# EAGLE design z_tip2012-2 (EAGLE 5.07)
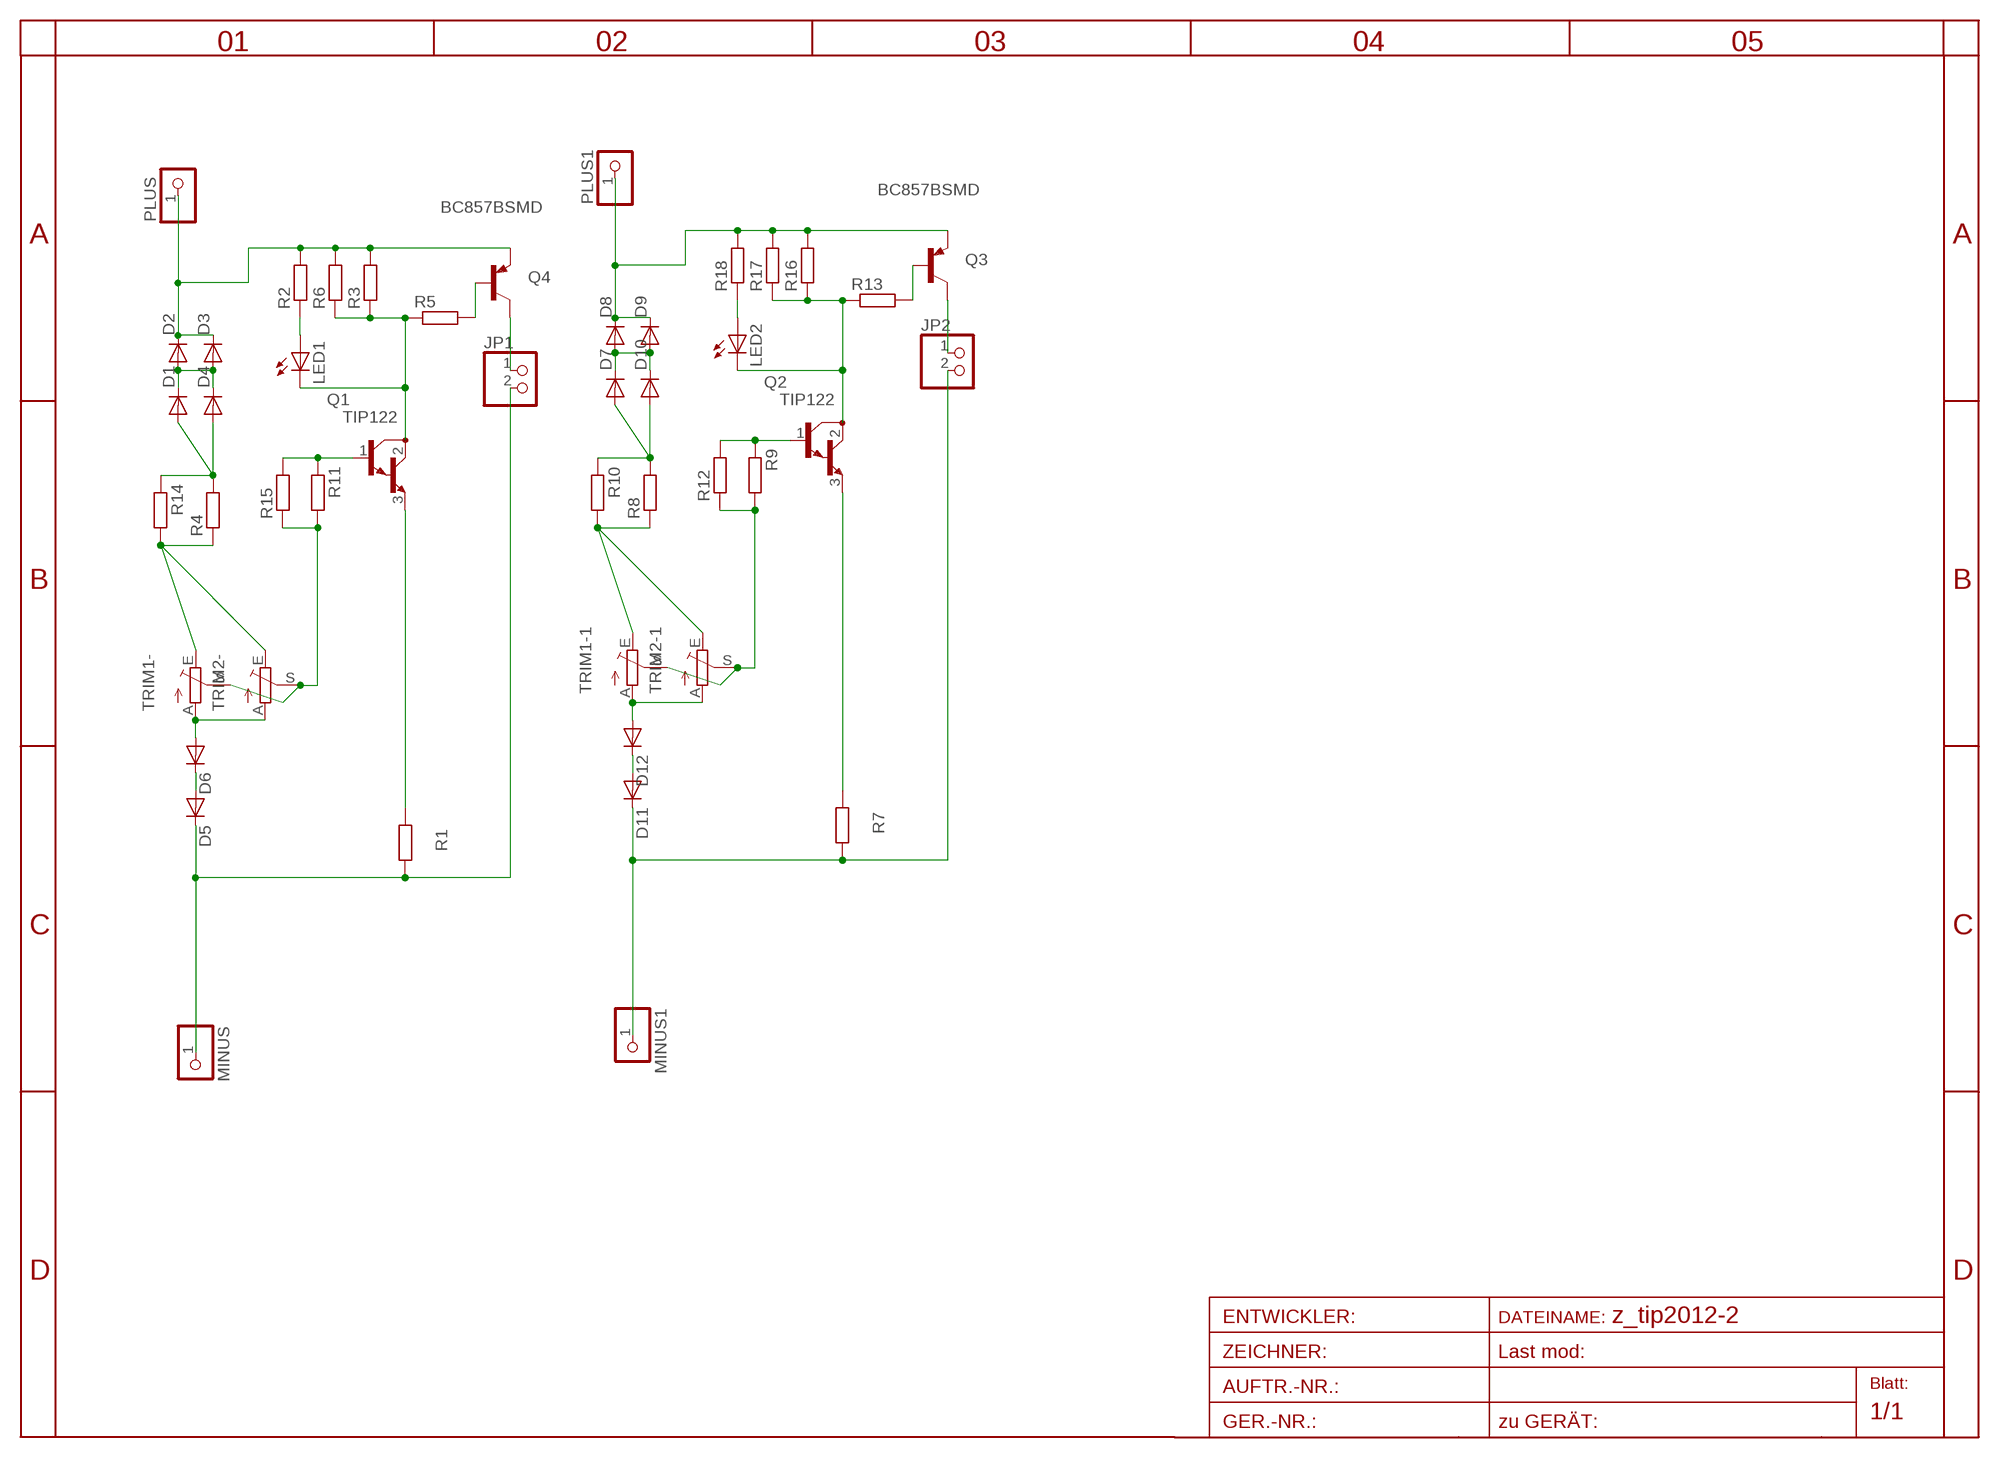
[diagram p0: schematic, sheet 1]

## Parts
D1  DIODE-MINIMELF  [MINIMELF]
D2  DIODE-MINIMELF  [MINIMELF]
D3  DIODE-D-2.5  [D-2.5]
D4  DIODE-D-2.5  [D-2.5]
D5  DIODE-MINIMELF  [MINIMELF]
D6  DIODE-MINIMELF  [MINIMELF]
D7  DIODE-MINIMELF  [MINIMELF]
D8  DIODE-MINIMELF  [MINIMELF]
D9  DIODE-D-2.5  [D-2.5]
D10  DIODE-D-2.5  [D-2.5]
D11  DIODE-MINIMELF  [MINIMELF]
D12  DIODE-MINIMELF  [MINIMELF]
JP1  PINHD-1X2  [1X02]
JP2  PINHD-1X2  [1X02]
LED1  LED3MM  [LED3MM]
LED2  LED3MM  [LED3MM]
MINUS  PINHD-1X10MM8  [1X01]
MINUS1  PINHD-1X10MM8  [1X01]
PLUS  PINHD-1X10MM8  [1X01]
PLUS1  PINHD-1X10MM8  [1X01]
Q1  TIP122  [TO220]
Q2  TIP122  [TO220]
Q3  BC857BSMD  [SOT23-BEC]
Q4  BC857BSMD  [SOT23-BEC]
R1  R-EU_0411/12  [0411/12]
R2  R-EU_R1206  [R1206]
R3  R-EU_CERAM55  [CERAM55]
R4  R-EU_R1206  [R1206]
R5  R-EU_R1206  [R1206]
R6  R-EU_CERAM55  [CERAM55]
R7  R-EU_0411/12  [0411/12]
R8  R-EU_R1206  [R1206]
R9  R-EU_0204/7  [0204/7]
R10  R-EU_0204/5  [0204/5]
R11  R-EU_0204/7  [0204/7]
R12  R-EU_R1206  [R1206]
R13  R-EU_R1206  [R1206]
R14  R-EU_0204/5  [0204/5]
R15  R-EU_R1206  [R1206]
R16  R-EU_CERAM55  [CERAM55]
R17  R-EU_CERAM55  [CERAM55]
R18  R-EU_R1206  [R1206]
TRIM1-  TRIM_EU-EVND_H  [EVND8AA]
TRIM1-1  TRIM_EU-CA6V  [CA6V]
TRIM2-  TRIM_EU-S64W  [S64W]
TRIM2-1  TRIM_EU-S64W  [S64W]

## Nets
B: R11.2 R15.1 TRIM1-.S TRIM2-.S
B1: R9.2 R12.1 TRIM1-1.S TRIM2-1.S
C: LED1.K(C) Q1.2(C) R3.1 R5.1 R6.1
C1: LED2.K(C) Q2.2(C) R13.1 R16.1 R17.1
E: Q1.3(E) R1.2
E1: Q2.3(E) R7.2
G: Q1.1(B) R11.1 R15.2
MINUS: D5.C JP1.2 MINUS.1 R1.1
MINUS1: D11.C JP2.2 MINUS1.1 R7.1
N$1: D1.A D4.A R4.2 R14.1
N$2: D1.C D2.A D3.A D4.C
N$3: R4.1 R14.2 TRIM1-.E TRIM2-.E
N$4: D5.A D6.C
N$6: LED1.A R2.1
N$7: D6.A TRIM1-.A TRIM2-.A
N$8: D7.C D8.A D9.A D10.C
N$9: Q4.B R5.2
N$11: R8.1 R10.2 TRIM1-1.E TRIM2-1.E
N$12: JP1.1 Q4.C
N$13: Q3.B R13.2
N$14: Q2.1(B) R9.1 R12.2
N$15: JP2.1 Q3.C
N$16: D7.A D10.A R8.2 R10.1
N$17: D11.A D12.C
N$18: LED2.A R18.1
N$19: D12.A TRIM1-1.A TRIM2-1.A
PLUS: D2.C D3.C PLUS.1 Q4.E R2.2 R3.2 R6.2
PLUS1: D8.C D9.C PLUS1.1 Q3.E R16.2 R17.2 R18.2

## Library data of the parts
D1-D12 = diode-1:DIODE-: DIODE
JP1 JP2 = pinhead:PINHD-1X2: PIN HEADER
LED1 LED2 = led:LED: LED
MINUS MINUS1 PLUS PLUS1 = pinhead:PINHD-1X1: PIN HEADER
Q1 Q2 = transistor-npn:TIP122*: NPN Darlington Transistor
Q3 Q4 = transistor-pnp:BC857*: PNP Transistror
R1-R18 = rcl:R-EU_: RESISTOR, European symbol
TRIM1- TRIM1-1 TRIM2- TRIM2-1 = pot:TRIM_EU-: POTENTIOMETER

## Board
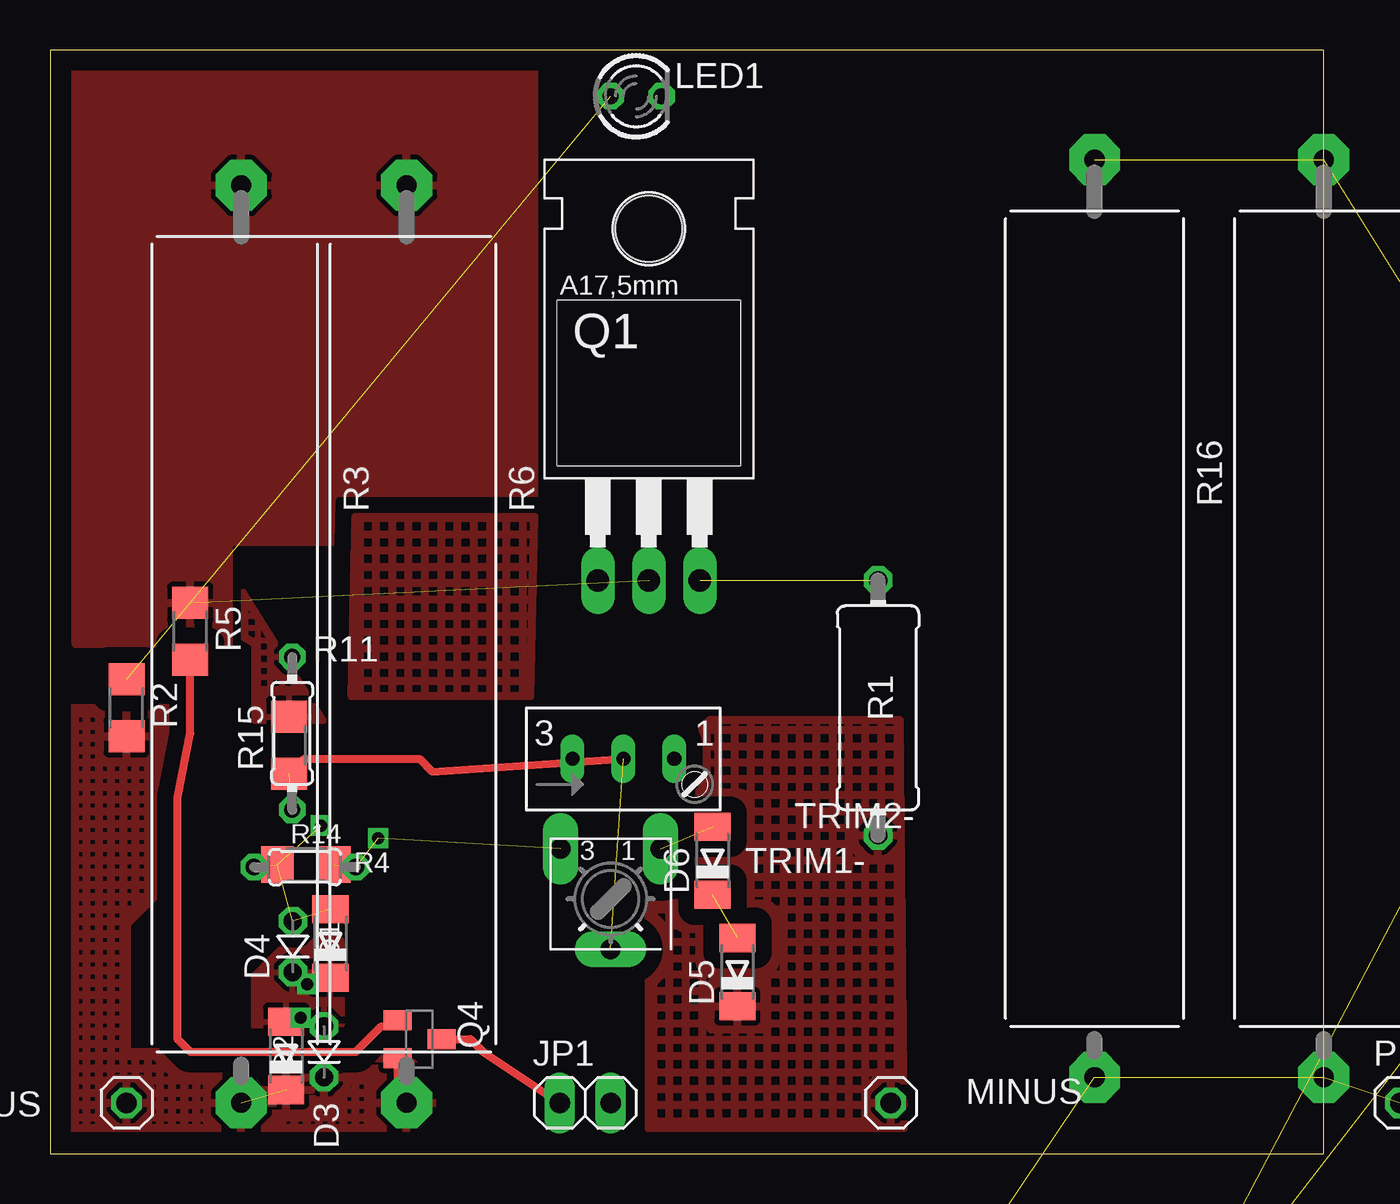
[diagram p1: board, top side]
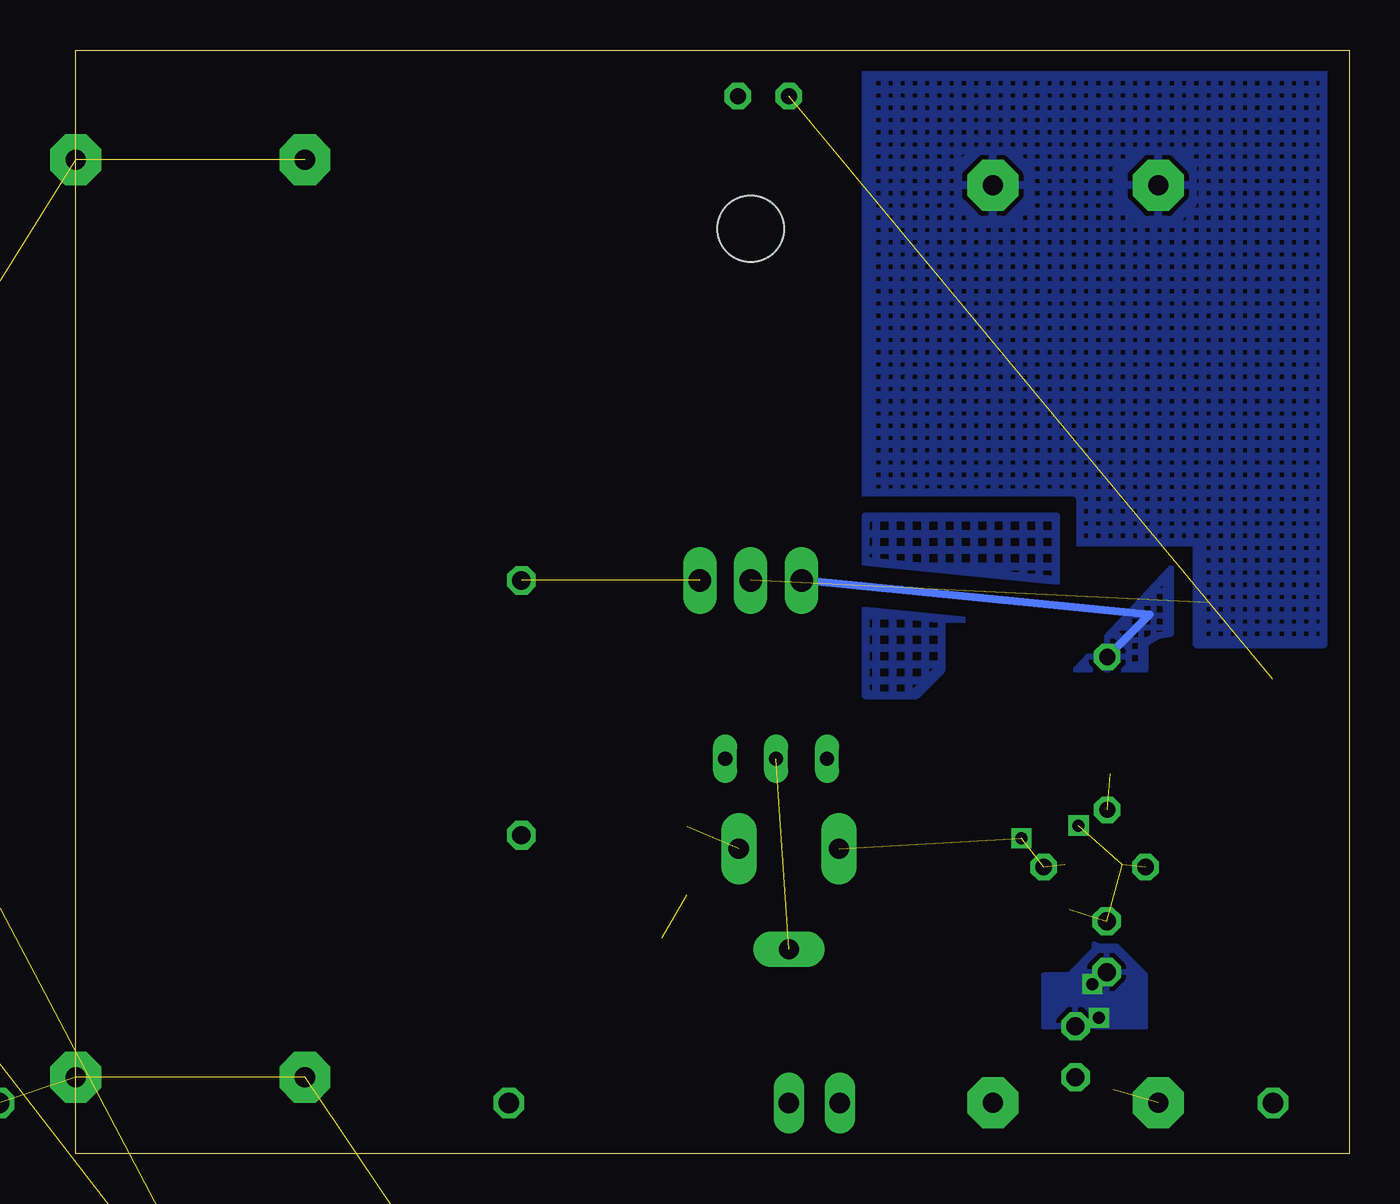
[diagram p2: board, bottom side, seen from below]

Size 63.5 x 55 mm. Coordinates in mm from the lower left corner, seen from the top.
Outline: 0,0 63.5,0 63.5,55 0,55 0,0
Copper layers (1*16): Top 0.035mm / dielectric 1.5mm / Bottom 0.035mm
Design rules "default": minimum track width 10mil, minimum drill 24mil, track to track 8mil, track to pad 8mil, pad to pad 8mil, via to via 8mil, smd to smd 8mil, copper to edge 40mil, drill to drill 8mil, minimum pad ring 10mil, minimum via ring 8mil, stop-mask expansion 4mil, vias tented up to drill 0mil, thermal gap 10mil

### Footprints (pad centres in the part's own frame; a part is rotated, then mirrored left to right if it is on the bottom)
MINIMELF = smd 1.4 x 1.8: A 1.7,0; C -1.7,0
D-2.5 = drill 0.9 octagon: A 1.27,0; C -1.27,0
1X02 = drill 1.016 long: 1 -1.27,0; 2 1.27,0
LED3MM = drill 0.813 octagon: A -1.27,0; K 1.27,0
1X01 = drill 1.016 octagon: 1 0,0
TO220 = drill 1.118 long: 1 -2.54,-6.35; 2 0,-6.35; 3 2.54,-6.35 | hole 3.302: 0,11.176
SOT23-BEC = smd 1 x 1.4: B -0.95,-1.1; C 0,1.1; E 0.95,-1.1
0411/12 = drill 0.914 octagon: 1 -6.35,0; 2 6.35,0
R1206 = smd 1.6 x 1.803: 1 -1.422,0; 2 1.422,0
CERAM55 = drill 1 pad 2.54 octagon: 1 -22.86,0; 2 22.86,0
0204/7 = drill 0.813 octagon: 1 -3.81,0; 2 3.81,0
0204/5 = drill 0.813 octagon: 1 -2.54,0; 2 2.54,0
EVND8AA = drill 1 pad 1.778 long: A -2.5,-2.5; E 2.5,-2.5; S 0,2.5
CA6V = drill 1.016 long: A -2.54,-2.54; E 2.54,-2.54; S 0,2.54
S64W = drill 0.7 long: A 2.54,1.27; E -2.54,1.27; S 0,1.27

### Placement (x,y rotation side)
D1  13.97,10.48 90 top
D2  11.77,4.88 90 top
D3  13.65,5.08 90 top
D4  12.1,10.32 90 top
D5  34.26,9.05 90 top
D6  33.02,14.61 90 top
D7  not placed on the board
D8  not placed on the board
D9  not placed on the board
D10  not placed on the board
D11  not placed on the board
D12  not placed on the board
JP1  26.67,2.54 0 top
JP2  not placed on the board
LED1  29.21,52.7 0 top
LED2  not placed on the board
MINUS  41.91,2.54 0 top
MINUS1  not placed on the board
PLUS  3.81,2.54 0 top
PLUS1  not placed on the board
Q1  29.84,34.92 0 top
Q2  not placed on the board
Q3  not placed on the board
Q4  18.41,5.71 270 top
R1  41.27,22.23 90 top
R2  3.81,22.23 270 top
R3  9.53,25.4 270 top
R4  12.75,14.41 180 top
R5  6.99,26.04 270 top
R6  17.78,25.4 270 top
R7  not placed on the board
R8  not placed on the board
R9  not placed on the board
R10  not placed on the board
R11  12.06,20.95 270 top
R12  not placed on the board
R13  not placed on the board
R14  12.7,14.29 0 top
R15  11.91,20.36 90 top
R16  52.07,26.67 270 top
R17  63.5,26.67 270 top
R18  not placed on the board
TRIM1-  27.94,12.7 180 top
TRIM1-1  not placed on the board
TRIM2-  28.57,18.41 0 top
TRIM2-1  not placed on the board

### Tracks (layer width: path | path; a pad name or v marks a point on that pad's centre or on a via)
B  (2 unrouted)
  Top 0.406: TRIM2-.S 19.05,19.05 18.41,19.68 12.66,19.68 R15.1
B1  (3 unrouted)
C  (1 unrouted)
  pour Bottom (isolate 0.813, rank 4, hatched): 24.13,30.48 7.62,30.48 7.62,25.4 1.27,25.4 1.27,54.61 24.13,54.61
  pour Top (isolate 0.813, rank 4): 24.13,30.48 8.89,30.48 8.89,25.4 1.27,25.4 1.27,54.61 24.13,54.61
C1  (4 unrouted)
E  (1 unrouted)
  pour Bottom (isolate 0.813, rank 2, hatched): 14.61,31.75 24.13,31.75 24.13,22.86 21.59,22.86 20.32,24.13 20.32,26.67 14.61,26.67
  pour Top (isolate 0.813, rank 2, hatched): 15.24,31.75 24.13,31.75 23.93,22.79 15.04,22.79
E1  (1 unrouted)
G
  Bottom 0.406: Q1.1 9.96,26.87 R11.1
  pour Bottom (isolate 0.406, rank 5, hatched): 8.89,29.21 8.9,25.9 9.5,25.8 10.16,25.4 10.16,24.13 13.67,24.13
  pour Top (isolate 0.406, rank 5, hatched): 8.89,29.21 8.9,25.9 9.5,25.8 10.16,25.4 10.16,21.59 13.67,21.59
MINUS
  pour Top (isolate 0.813, rank 6, hatched): 32.88,21.62 42.34,21.62 42.55,1.27 29.84,1.27 29.84,19.05
MINUS1  (3 unrouted)
N$1  (via drill 0.6)  (4 unrouted)
  other vias: 13.5,16.36
N$2  (via drill 0.6)
  other vias: 12.49,6.78 12.81,8.46
  pour Bottom (isolate 0.406, rank 4): 11.43,10.16 12.7,11.43 12.7,10.16 13.97,8.89 15.24,8.89 15.24,6.35 10.16,6.35 10.16,8.89
  pour Top (isolate 0.61, rank 4): 10.16,8.89 12.7,11.43 14.5,10.66 14.57,9.69 14.54,8.99 14.54,6.45 10.16,6.35
N$3  (via drill 0.6)  (3 unrouted)
  other vias: 16.34,15.72
N$4  (1 unrouted)
N$6  (1 unrouted)
N$7  (1 unrouted)
N$8  (3 unrouted)
N$9
  Top 0.406: R5.2 6.99,20.95 6.35,17.78 6.35,5.71 6.99,5.08 15.24,5.08 16.51,6.35 17,6.35 Q4.B
N$11  (3 unrouted)
N$12
  Top 0.406: Q4.C 20.95,5.71 21.59,5.08 JP1.1
N$13  (1 unrouted)
N$14  (2 unrouted)
N$15  (1 unrouted)
N$16  (3 unrouted)
N$17  (1 unrouted)
N$18  (1 unrouted)
N$19  (2 unrouted)
PLUS  (1 unrouted)
  Top 0.406: Q4.E 17.32,3 R6.2
  pour Top (isolate 0.813, rank 5, hatched): 0,22.23 8.89,22.23 8.89,16.51 3.81,11.43 3.81,5.08 13.97,5.08 19.05,4.45 19.05,1.27 0,1.27
PLUS1  (6 unrouted)

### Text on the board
tTest: fuse | 1R8 10W | 101 | 202 | minus | plus | C..A
bTest: TIP122 | fuse | 1R8 10W | 101 | 202 | minus | plus | C..A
